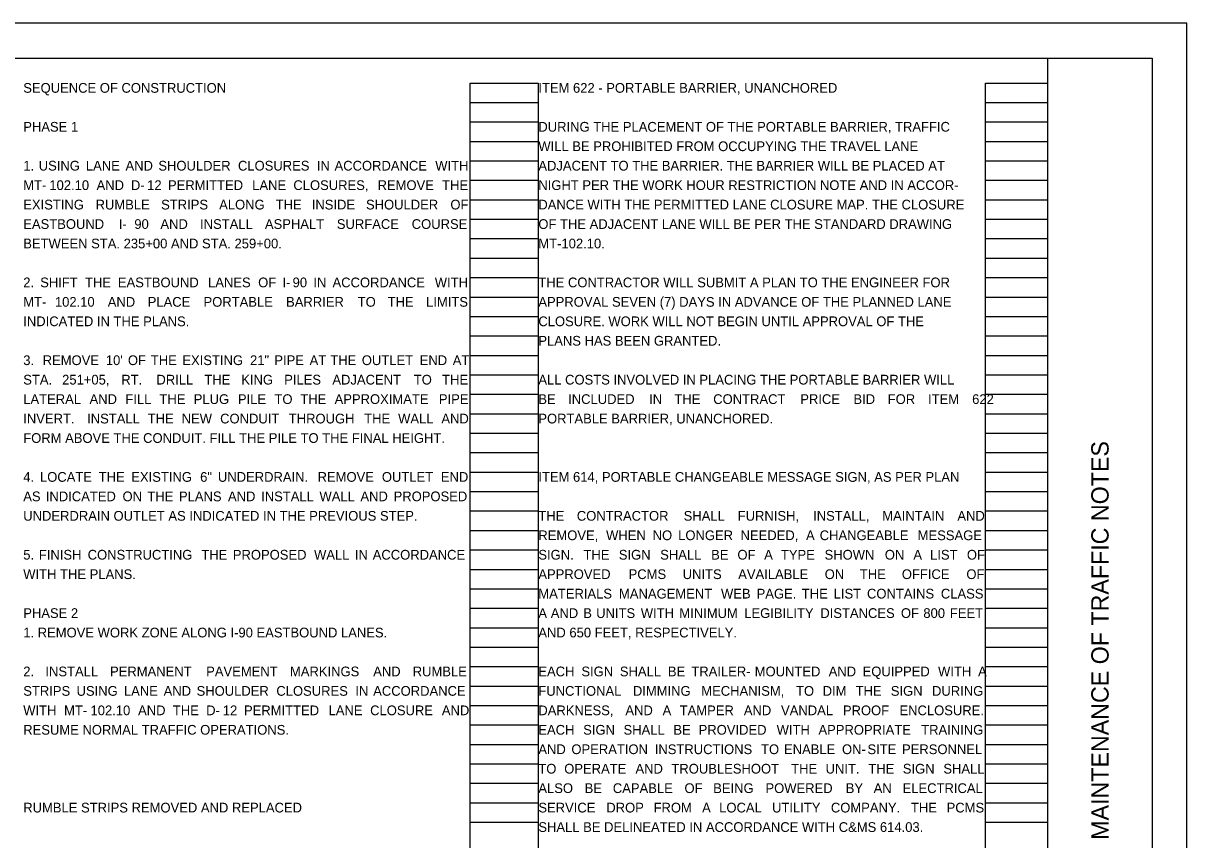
# Model space of a CAD drawing. Extents: x 0 to 34, y 0 to 22.
# Drawn here: x 17.24 to 34, y 10.25 to 22 of the extents above; entities that cross this region are included whole.
import ezdxf

# ---------------------------------------------------------------- set-up
doc = ezdxf.new("R2010")
doc.units = 0
for name, color, linetype in [('SH_Border', 7, 'Continuous'), ('SH_Cut_Line', 7, 'Continuous'), ('SH_Data', 7, 'Continuous'), ('SH_Text', 7, 'Continuous')]:
    doc.layers.add(name, color=color, linetype=linetype)

msp = doc.modelspace()

# ---------------------------------------------------------------- linework, layer by layer
at = {"layer": 'SH_Border'}
msp.add_line((32, 0.5), (32, 21.5), dxfattribs=at)
msp.add_lwpolyline([(1.5, 21.5), (33.5, 21.5), (33.5, 0.5), (1.5, 0.5)], close=True, dxfattribs=at)
at = {"layer": 'SH_Cut_Line'}
msp.add_lwpolyline([(0, 0), (34, 0), (34, 22), (0, 22)], close=True, dxfattribs=at)
at = {"layer": 'SH_Data'}
for p, q in [((23.68, 0.98), (23.68, 21.14)), ((23.68, 21.14), (24.66, 21.14)), ((24.66, 0.98), (24.66, 21.14)), ((31.1, 0.98), (31.1, 21.14)), ((31.1, 21.14), (32, 21.14)), ((32, 0.98), (32, 21.14)), ((23.68, 20.86), (24.66, 20.86)), ((31.1, 20.86), (32, 20.86)), ((23.68, 20.58), (24.66, 20.58)), ((31.1, 20.58), (32, 20.58)), ((23.68, 20.3), (24.66, 20.3)), ((31.1, 20.3), (32, 20.3)), ((23.68, 20.02), (24.66, 20.02)), ((31.1, 20.02), (32, 20.02)), ((23.68, 19.74), (24.66, 19.74)), ((31.1, 19.74), (32, 19.74)), ((23.68, 19.46), (24.66, 19.46)), ((31.1, 19.46), (32, 19.46)), ((23.68, 19.18), (24.66, 19.18)), ((31.1, 19.18), (32, 19.18)), ((23.68, 18.9), (24.66, 18.9)), ((31.1, 18.9), (32, 18.9)), ((23.68, 18.62), (24.66, 18.62)), ((31.1, 18.62), (32, 18.62)), ((23.68, 18.34), (24.66, 18.34)), ((31.1, 18.34), (32, 18.34)), ((23.68, 18.06), (24.66, 18.06)), ((31.1, 18.06), (32, 18.06)), ((23.68, 17.78), (24.66, 17.78)), ((31.1, 17.78), (32, 17.78)), ((23.68, 17.5), (24.66, 17.5)), ((31.1, 17.5), (32, 17.5)), ((23.68, 17.22), (24.66, 17.22)), ((31.1, 17.22), (32, 17.22)), ((23.68, 16.94), (24.66, 16.94)), ((31.1, 16.94), (32, 16.94)), ((23.68, 16.66), (24.66, 16.66)), ((31.1, 16.66), (32, 16.66)), ((23.68, 16.38), (24.66, 16.38)), ((31.1, 16.38), (32, 16.38)), ((23.68, 16.1), (24.66, 16.1)), ((31.1, 16.1), (32, 16.1)), ((23.68, 15.82), (24.66, 15.82)), ((31.1, 15.82), (32, 15.82)), ((23.68, 15.54), (24.66, 15.54)), ((31.1, 15.54), (32, 15.54)), ((23.68, 15.26), (24.66, 15.26)), ((31.1, 15.26), (32, 15.26)), ((23.68, 14.98), (24.66, 14.98)), ((31.1, 14.98), (32, 14.98)), ((23.68, 14.7), (24.66, 14.7)), ((31.1, 14.7), (32, 14.7)), ((23.68, 14.42), (24.66, 14.42)), ((31.1, 14.42), (32, 14.42)), ((23.68, 14.14), (24.66, 14.14)), ((31.1, 14.14), (32, 14.14)), ((23.68, 13.86), (24.66, 13.86)), ((31.1, 13.86), (32, 13.86)), ((23.68, 13.58), (24.66, 13.58)), ((31.1, 13.58), (32, 13.58)), ((23.68, 13.3), (24.66, 13.3)), ((31.1, 13.3), (32, 13.3)), ((23.68, 13.02), (24.66, 13.02)), ((31.1, 13.02), (32, 13.02)), ((23.68, 12.74), (24.66, 12.74)), ((31.1, 12.74), (32, 12.74)), ((23.68, 12.46), (24.66, 12.46)), ((31.1, 12.46), (32, 12.46)), ((23.68, 12.18), (24.66, 12.18)), ((31.1, 12.18), (32, 12.18)), ((23.68, 11.9), (24.66, 11.9)), ((31.1, 11.9), (32, 11.9)), ((23.68, 11.62), (24.66, 11.62)), ((31.1, 11.62), (32, 11.62)), ((23.68, 11.34), (24.66, 11.34)), ((31.1, 11.34), (32, 11.34)), ((23.68, 11.06), (24.66, 11.06)), ((31.1, 11.06), (32, 11.06)), ((23.68, 10.78), (24.66, 10.78)), ((31.1, 10.78), (32, 10.78)), ((23.68, 10.5), (24.66, 10.5)), ((31.1, 10.5), (32, 10.5))]:
    msp.add_line(p, q, dxfattribs=at)

# ---------------------------------------------------------------- texts
msp.add_text('MAINTENANCE OF TRAFFIC NOTES', height=0.25, rotation=90, dxfattribs=at).set_placement((32.875, 10.247))
at = {"layer": 'SH_Text'}
for s, p in [('SEQUENCE OF CONSTRUCTION', (17.24, 21)), ('ITEM 622 - PORTABLE BARRIER, UNANCHORED', (24.66, 21)), ('PHASE 1', (17.24, 20.44)), ('DURING THE PLACEMENT OF THE PORTABLE BARRIER, TRAFFIC ', (24.66, 20.44)), ('WILL BE PROHIBITED FROM OCCUPYING THE TRAVEL LANE ', (24.66, 20.16)), ('1. ', (17.24, 19.88)), ('USING ', (17.463, 19.88)), ('LANE ', (18.142, 19.88)), ('AND ', (18.713, 19.88)), ('SHOULDER ', (19.186, 19.88)), ('CLOSURES ', (20.333, 19.88)), ('IN ', (21.469, 19.88)), ('ACCORDANCE ', (21.724, 19.88)), ('WITH ', (23.175, 19.88)), ('ADJACENT TO THE BARRIER. THE BARRIER WILL BE PLACED AT ', (24.66, 19.88)), ('MT-', (17.24, 19.6)), ('102.10 ', (17.616, 19.6)), ('AND ', (18.296, 19.6)), ('D-', (18.791, 19.6)), ('12 ', (19.025, 19.6)), ('PERMITTED ', (19.325, 19.6)), ('LANE ', (20.538, 19.6)), ('CLOSURES, ', (21.131, 19.6)), ('REMOVE ', (22.344, 19.6)), ('THE ', (23.274, 19.6)), ('NIGHT PER THE WORK HOUR RESTRICTION NOTE AND IN ACCOR-', (24.66, 19.6)), ('EXISTING ', (17.24, 19.32)), ('RUMBLE ', (18.282, 19.32)), ('STRIPS ', (19.226, 19.32)), ('ALONG ', (20.062, 19.32)), ('THE ', (20.876, 19.32)), ('INSIDE ', (21.396, 19.32)), ('SHOULDER ', (22.177, 19.32)), ('OF ', (23.393, 19.32)), ('DANCE WITH THE PERMITTED LANE CLOSURE MAP. THE CLOSURE ', (24.66, 19.32)), ('EASTBOUND ', (17.24, 19.04)), ('I-', (18.616, 19.04)), ('90 ', (18.84, 19.04)), ('AND ', (19.216, 19.04)), ('INSTALL ', (19.787, 19.04)), ('ASPHALT ', (20.721, 19.04)), ('SURFACE ', (21.757, 19.04)), ('COURSE ', (22.836, 19.04)), ('OF THE ADJACENT LANE WILL BE PER THE STANDARD DRAWING ', (24.66, 19.04)), ('BETWEEN STA. 235+00 AND STA. 259+00.', (17.24, 18.76)), ('MT-102.10.', (24.66, 18.76)), ('2. ', (17.24, 18.2)), ('SHIFT ', (17.484, 18.2)), ('THE ', (18.13, 18.2)), ('EASTBOUND ', (18.603, 18.2)), ('LANES ', (19.902, 18.2)), ('OF ', (20.624, 18.2)), ('I-', (20.974, 18.2)), ('90 ', (21.12, 18.2)), ('IN ', (21.419, 18.2)), ('ACCORDANCE ', (21.695, 18.2)), ('WITH ', (23.168, 18.2)), ('THE CONTRACTOR WILL SUBMIT A PLAN TO THE ENGINEER FOR ', (24.66, 18.2)), ('MT-', (17.24, 17.92)), ('102.10 ', (17.696, 17.92)), ('AND ', (18.457, 17.92)), ('PLACE ', (19.033, 17.92)), ('PORTABLE ', (19.837, 17.92)), ('BARRIER ', (21.026, 17.92)), ('TO ', (22.058, 17.92)), ('THE ', (22.489, 17.92)), ('LIMITS ', (23.043, 17.92)), ('APPROVAL SEVEN (7) DAYS IN ADVANCE OF THE PLANNED LANE ', (24.66, 17.92)), ('INDICATED IN THE PLANS.', (17.24, 17.64)), ('CLOSURE. WORK WILL NOT BEGIN UNTIL APPROVAL OF THE ', (24.66, 17.64)), ('PLANS HAS BEEN GRANTED.', (24.66, 17.36)), ('3.  ', (17.24, 17.08)), ('REMOVE ', (17.52, 17.08)), ("10' ", (18.43, 17.08)), ('OF ', (18.748, 17.08)), ('THE ', (19.078, 17.08)), ('EXISTING ', (19.532, 17.08)), ('21" ', (20.507, 17.08)), ('PIPE ', (20.857, 17.08)), ('AT ', (21.365, 17.08)), ('THE ', (21.663, 17.08)), ('OUTLET ', (22.117, 17.08)), ('END ', (22.951, 17.08)), ('AT ', (23.427, 17.08)), ('STA. ', (17.24, 16.8)), ('251+05, ', (17.8, 16.8)), ('RT.  ', (18.652, 16.8)), ('DRILL ', (19.158, 16.8)), ('THE ', (19.849, 16.8)), ('KING ', (20.38, 16.8)), ('PILES ', (20.999, 16.8)), ('ADJACENT ', (21.693, 16.8)), ('TO ', (22.866, 16.8)), ('THE ', (23.274, 16.8)), ('ALL COSTS INVOLVED IN PLACING THE PORTABLE BARRIER WILL', (24.66, 16.8)), ('LATERAL ', (17.24, 16.52)), ('AND ', (18.195, 16.52)), ('FILL ', (18.711, 16.52)), ('THE ', (19.202, 16.52)), ('PLUG ', (19.696, 16.52)), ('PILE ', (20.332, 16.52)), ('TO ', (20.859, 16.52)), ('THE ', (21.231, 16.52)), ('APPROXIMATE ', (21.725, 16.52)), ('PIPE ', (23.227, 16.52)), ('BE ', (24.66, 16.52)), ('INCLUDED ', (25.089, 16.52)), ('IN ', (26.256, 16.52)), ('THE ', (26.62, 16.52)), ('CONTRACT ', (27.179, 16.52)), ('PRICE ', (28.433, 16.52)), ('BID ', (29.199, 16.52)), ('FOR ', (29.693, 16.52)), ('ITEM ', (30.274, 16.52)), ('622 ', (30.909, 16.52)), ('INVERT.  ', (17.24, 16.24)), ('INSTALL ', (18.16, 16.24)), ('THE ', (19.033, 16.24)), ('NEW ', (19.522, 16.24)), ('CONDUIT ', (20.076, 16.24)), ('THROUGH ', (21.065, 16.24)), ('THE ', (22.151, 16.24)), ('WALL ', (22.64, 16.24)), ('AND ', (23.263, 16.24)), ('PORTABLE BARRIER, UNANCHORED.', (24.66, 16.24)), ('FORM ABOVE THE CONDUIT. FILL THE PILE TO THE FINAL HEIGHT.', (17.24, 15.96)), ('4. ', (17.24, 15.4)), ('LOCATE ', (17.481, 15.4)), ('THE ', (18.327, 15.4)), ('EXISTING ', (18.796, 15.4)), ('6" ', (19.788, 15.4)), ('UNDERDRAIN. ', (20.044, 15.4)), ('REMOVE ', (21.48, 15.4)), ('OUTLET ', (22.406, 15.4)), ('END ', (23.256, 15.4)), ('ITEM 614, PORTABLE CHANGEABLE MESSAGE SIGN, AS PER PLAN', (24.66, 15.4)), ('AS ', (17.24, 15.12)), ('INDICATED ', (17.565, 15.12)), ('ON ', (18.67, 15.12)), ('THE ', (19.028, 15.12)), ('PLANS ', (19.483, 15.12)), ('AND ', (20.189, 15.12)), ('INSTALL ', (20.667, 15.12)), ('WALL ', (21.507, 15.12)), ('AND ', (22.097, 15.12)), ('PROPOSED ', (22.575, 15.12)), ('UNDERDRAIN OUTLET AS INDICATED IN THE PREVIOUS STEP.', (17.24, 14.84)), ('THE ', (24.66, 14.84)), ('CONTRACTOR ', (25.214, 14.84)), ('SHALL ', (26.753, 14.84)), ('FURNISH, ', (27.532, 14.84)), ('INSTALL, ', (28.618, 14.84)), ('MAINTAIN ', (29.614, 14.84)), ('AND ', (30.696, 14.84)), ('REMOVE, ', (24.66, 14.56)), ('WHEN ', (25.636, 14.56)), ('NO ', (26.307, 14.56)), ('LONGER ', (26.674, 14.56)), ('NEEDED, ', (27.573, 14.56)), ('A ', (28.516, 14.56)), ('CHANGEABLE ', (28.713, 14.56)), ('MESSAGE ', (30.124, 14.56)), ('5. ', (17.24, 14.28)), ('FINISH ', (17.465, 14.28)), ('CONSTRUCTING ', (18.168, 14.28)), ('THE ', (19.805, 14.28)), ('PROPOSED ', (20.259, 14.28)), ('WALL ', (21.429, 14.28)), ('IN ', (22.017, 14.28)), ('ACCORDANCE ', (22.274, 14.28)), ('SIGN. ', (24.66, 14.28)), ('THE ', (25.31, 14.28)), ('SIGN ', (25.819, 14.28)), ('SHALL ', (26.415, 14.28)), ('BE ', (27.149, 14.28)), ('OF ', (27.528, 14.28)), ('A ', (27.913, 14.28)), ('TYPE ', (28.154, 14.28)), ('SHOWN ', (28.783, 14.28)), ('ON ', (29.651, 14.28)), ('A ', (30.062, 14.28)), ('LIST ', (30.303, 14.28)), ('OF ', (30.833, 14.28)), ('WITH THE PLANS.', (17.24, 14)), ('APPROVED ', (24.66, 14)), ('PCMS ', (25.96, 14)), ('UNITS ', (26.739, 14)), ('AVAILABLE ', (27.539, 14)), ('ON ', (28.785, 14)), ('THE ', (29.291, 14)), ('OFFICE ', (29.896, 14)), ('OF ', (30.826, 14)), ('MATERIALS ', (24.66, 13.72)), ('MANAGEMENT ', (25.822, 13.72)), ('WEB ', (27.291, 13.72)), ('PAGE. ', (27.804, 13.72)), ('THE ', (28.455, 13.72)), ('LIST ', (28.914, 13.72)), ('CONTAINS ', (29.394, 13.72)), ('CLASS ', (30.458, 13.72)), ('PHASE 2', (17.24, 13.44)), ('A ', (24.66, 13.44)), ('AND ', (24.839, 13.44)), ('B ', (25.307, 13.44)), ('UNITS ', (25.493, 13.44)), ('WITH ', (26.136, 13.44)), ('MINIMUM ', (26.691, 13.44)), ('LEGIBILITY ', (27.626, 13.44)), ('DISTANCES ', (28.722, 13.44)), ('OF ', (29.883, 13.44)), ('800 ', (30.206, 13.44)), ('FEET ', (30.588, 13.44)), ('1. REMOVE WORK ZONE ALONG I-90 EASTBOUND LANES.', (17.24, 13.16)), ('AND 650 FEET, RESPECTIVELY.', (24.66, 13.16)), ('2. ', (17.24, 12.6)), ('INSTALL ', (17.559, 12.6)), ('PERMANENT ', (18.49, 12.6)), ('PAVEMENT ', (19.875, 12.6)), ('MARKINGS ', (21.082, 12.6)), ('AND ', (22.281, 12.6)), ('RUMBLE ', (22.85, 12.6)), ('EACH ', (24.66, 12.6)), ('SIGN ', (25.28, 12.6)), ('SHALL ', (25.834, 12.6)), ('BE ', (26.526, 12.6)), ('TRAILER-', (26.864, 12.6)), ('MOUNTED ', (27.777, 12.6)), ('AND ', (28.842, 12.6)), ('EQUIPPED ', (29.331, 12.6)), ('WITH ', (30.418, 12.6)), ('A ', (30.994, 12.6)), ('STRIPS ', (17.24, 12.32)), ('USING ', (18.008, 12.32)), ('LANE ', (18.69, 12.32)), ('AND ', (19.262, 12.32)), ('SHOULDER ', (19.737, 12.32)), ('CLOSURES ', (20.886, 12.32)), ('IN ', (22.024, 12.32)), ('ACCORDANCE ', (22.281, 12.32)), ('FUNCTIONAL ', (24.66, 12.32)), ('DIMMING ', (26.022, 12.32)), ('MECHANISM, ', (27.007, 12.32)), ('TO ', (28.372, 12.32)), ('DIM ', (28.756, 12.32)), ('THE ', (29.23, 12.32)), ('SIGN ', (29.737, 12.32)), ('DURING ', (30.331, 12.32)), ('WITH ', (17.24, 12.04)), ('MT-', (17.828, 12.04)), ('102.10 ', (18.209, 12.04)), ('AND ', (18.894, 12.04)), ('THE ', (19.395, 12.04)), ('D-', (19.875, 12.04)), ('12 ', (20.114, 12.04)), ('PERMITTED ', (20.42, 12.04)), ('LANE ', (21.638, 12.04)), ('CLOSURE ', (22.237, 12.04)), ('AND ', (23.27, 12.04)), ('DARKNESS, ', (24.66, 12.04)), ('AND ', (25.914, 12.04)), ('A ', (26.45, 12.04)), ('TAMPER ', (26.696, 12.04)), ('AND ', (27.62, 12.04)), ('VANDAL ', (28.156, 12.04)), ('PROOF ', (29.047, 12.04)), ('ENCLOSURE. ', (29.862, 12.04)), ('RESUME NORMAL TRAFFIC OPERATIONS.', (17.24, 11.76)), ('EACH ', (24.66, 11.76)), ('SIGN ', (25.306, 11.76)), ('SHALL ', (25.887, 11.76)), ('BE ', (26.605, 11.76)), ('PROVIDED ', (26.969, 11.76)), ('WITH ', (28.093, 11.76)), ('APPROPRIATE ', (28.695, 11.76)), ('TRAINING ', (30.175, 11.76)), ('AND ', (24.66, 11.48)), ('OPERATION ', (25.136, 11.48)), ('INSTRUCTIONS ', (26.337, 11.48)), ('TO ', (27.868, 11.48)), ('ENABLE ', (28.199, 11.48)), ('ON-', (29.034, 11.48)), ('SITE ', (29.401, 11.48)), ('PERSONNEL ', (29.899, 11.48)), ('TO ', (24.66, 11.2)), ('OPERATE ', (25.033, 11.2)), ('AND ', (26.059, 11.2)), ('TROUBLESHOOT ', (26.577, 11.2)), ('THE ', (28.302, 11.2)), ('UNIT. ', (28.798, 11.2)), ('THE ', (29.414, 11.2)), ('SIGN ', (29.91, 11.2)), ('SHALL ', (30.494, 11.2)), ('ALSO ', (24.66, 10.92)), ('CAPABLE ', (25.733, 10.92)), ('OF ', (26.765, 10.92)), ('BEING ', (27.179, 10.92)), ('POWERED ', (27.932, 10.92)), ('ELECTRICAL ', (29.907, 10.92)), ('BE ', (25.327, 10.92)), ('BY ', (29.088, 10.92)), ('AN ', (29.49, 10.92)), ('RUMBLE STRIPS REMOVED AND REPLACED', (17.24, 10.64)), ('SERVICE ', (24.66, 10.64)), ('DROP ', (25.639, 10.64)), ('FROM ', (26.32, 10.64)), ('A ', (27.019, 10.64)), ('LOCAL ', (27.265, 10.64)), ('UTILITY ', (28.027, 10.64)), ('COMPANY. ', (28.874, 10.64)), ('THE ', (30.027, 10.64)), ('PCMS ', (30.541, 10.64)), ('SHALL BE DELINEATED IN ACCORDANCE WITH C&MS 614.03.', (24.66, 10.36))]:
    msp.add_text(s, height=0.14, dxfattribs=at).set_placement(p)

doc.saveas('drawing.dxf')
